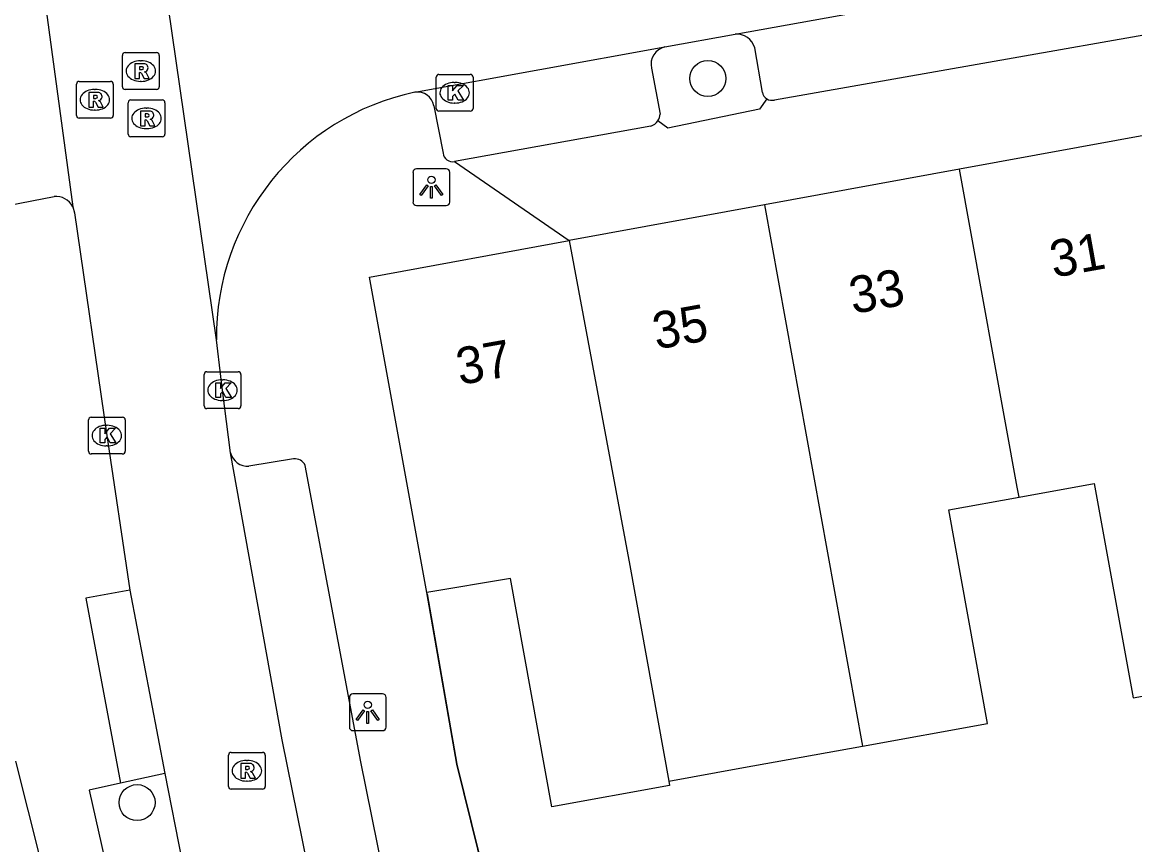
# Model space of a CAD drawing. Extents: x 159718 to 160783, y 383290 to 384030.
# Drawn here: x 160233.32 to 160263.54, y 383643.06 to 383665.41 of the extents above; entities that cross this region are included whole.
import ezdxf

# ---------------------------------------------------------------- set-up
doc = ezdxf.new("R2010")
doc.units = 0
for name, color, linetype in [('IMGEO_Boom', 7, 'Continuous'), ('IMGEO_Kolk', 7, 'Continuous'), ('IMGEO_Lichtpunt', 7, 'Continuous'), ('IMGEO_Muur', 7, 'Continuous'), ('IMGEO_Pand', 7, 'Continuous'), ('IMGEO_Pand_nummerreeks', 7, 'Continuous'), ('IMGEO_Parkeervlak_open', 7, 'Continuous'), ('IMGEO_Rijbaan_lokaal_open', 7, 'Continuous'), ('IMGEO_Rioolput', 7, 'Continuous'), ('IMGEO_Voetpad_open', 7, 'Continuous')]:
    doc.layers.add(name, color=color, linetype=linetype)

msp = doc.modelspace()

# ---------------------------------------------------------------- linework, layer by layer
at = {"layer": 'IMGEO_Boom'}
for centre in [(160251.944, 383663.882), (160236.435, 383644.202)]:
    msp.add_circle(centre, 0.489, dxfattribs=at)
at = {"layer": 'IMGEO_Kolk'}
for p, q in [((160244.563, 383663.069), (160244.563, 383663.921)), ((160244.638, 383663.995), (160245.49, 383663.995)), ((160245.564, 383663.921), (160245.564, 383663.069)), ((160245.051, 383663.775), (160245.076, 383663.775)), ((160245.074, 383663.215), (160245.049, 383663.215)), ((160245.49, 383662.995), (160244.638, 383662.995)), ((160238.257, 383654.986), (160238.257, 383655.838)), ((160238.332, 383655.912), (160239.184, 383655.912)), ((160238.745, 383655.692), (160238.77, 383655.692)), ((160239.258, 383655.838), (160239.258, 383654.986)), ((160238.768, 383655.132), (160238.743, 383655.132)), ((160239.184, 383654.912), (160238.332, 383654.912)), ((160235.114, 383653.751), (160235.114, 383654.603)), ((160235.189, 383654.677), (160236.041, 383654.677)), ((160235.602, 383654.457), (160235.627, 383654.457)), ((160236.115, 383654.603), (160236.115, 383653.751)), ((160235.625, 383653.897), (160235.6, 383653.897)), ((160236.041, 383653.677), (160235.189, 383653.677))]:
    msp.add_line(p, q, dxfattribs=at)
for points in [[(160244.563, 383663.069), (160244.563, 383663.921)], [(160244.638, 383663.995), (160245.49, 383663.995)], [(160245.564, 383663.921), (160245.564, 383663.069)], [(160244.884, 383663.695), (160245.007, 383663.695), (160245.007, 383663.544), (160245.137, 383663.695), (160245.301, 383663.695), (160245.155, 383663.544), (160245.308, 383663.295), (160245.156, 383663.295), (160245.071, 383663.459), (160245.007, 383663.392), (160245.007, 383663.295), (160244.884, 383663.295), (160244.884, 383663.695)], [(160245.49, 383662.995), (160244.638, 383662.995)], [(160238.257, 383654.986), (160238.257, 383655.838)], [(160238.332, 383655.912), (160239.184, 383655.912)], [(160239.258, 383655.838), (160239.258, 383654.986)], [(160238.578, 383655.612), (160238.701, 383655.612), (160238.701, 383655.461), (160238.831, 383655.612), (160238.995, 383655.612), (160238.849, 383655.461), (160239.002, 383655.212), (160238.85, 383655.212), (160238.765, 383655.376), (160238.701, 383655.309), (160238.701, 383655.212), (160238.578, 383655.212), (160238.578, 383655.612)], [(160239.184, 383654.912), (160238.332, 383654.912)], [(160235.114, 383653.751), (160235.114, 383654.603)], [(160235.189, 383654.677), (160236.041, 383654.677)], [(160236.115, 383654.603), (160236.115, 383653.751)], [(160235.435, 383654.377), (160235.558, 383654.377), (160235.558, 383654.226), (160235.688, 383654.377), (160235.852, 383654.377), (160235.706, 383654.226), (160235.859, 383653.977), (160235.707, 383653.977), (160235.622, 383654.141), (160235.558, 383654.074), (160235.558, 383653.977), (160235.435, 383653.977), (160235.435, 383654.377)], [(160236.041, 383653.677), (160235.189, 383653.677)]]:
    msp.add_lwpolyline(points, dxfattribs=at)
for centre, start, end in [((160244.64, 383663.919), 91.552, 178.448), ((160244.64, 383663.919), 91.552, 178.448), ((160245.488, 383663.919), 1.552, 88.448), ((160245.488, 383663.919), 1.552, 88.448), ((160244.64, 383663.071), 181.552, 268.448), ((160244.64, 383663.071), 181.552, 268.448), ((160245.488, 383663.071), 271.552, 358.448), ((160245.488, 383663.071), 271.552, 358.448), ((160238.334, 383655.836), 91.552, 178.448), ((160238.334, 383655.836), 91.552, 178.448), ((160239.182, 383655.836), 1.552, 88.448), ((160239.182, 383655.836), 1.552, 88.448), ((160238.334, 383654.988), 181.552, 268.448), ((160238.334, 383654.988), 181.552, 268.448), ((160239.182, 383654.988), 271.552, 358.448), ((160239.182, 383654.988), 271.552, 358.448), ((160235.191, 383654.601), 91.552, 178.448), ((160235.191, 383654.601), 91.552, 178.448), ((160236.039, 383654.601), 1.552, 88.448), ((160236.039, 383654.601), 1.552, 88.448), ((160235.191, 383653.753), 181.552, 268.448), ((160235.191, 383653.753), 181.552, 268.448), ((160236.039, 383653.753), 271.552, 358.448), ((160236.039, 383653.753), 271.552, 358.448)]:
    msp.add_arc(centre, 0.0765, start, end, dxfattribs=at)
for centre, major_axis, ratio, start_param, end_param in [((160245.05, 383663.495), (-0.387, 0.002), 0.722429, 4.712389, 7.853982), ((160245.075, 383663.495), (-0.39, 0.002), 0.717154, 1.570796, 4.712389), ((160238.744, 383655.412), (-0.387, 0.002), 0.722429, 4.712389, 7.853982), ((160238.769, 383655.412), (-0.39, 0.002), 0.717154, 1.570796, 4.712389), ((160235.601, 383654.177), (-0.387, 0.002), 0.722429, 4.712389, 7.853982), ((160235.626, 383654.177), (-0.39, 0.002), 0.717154, 1.570796, 4.712389)]:
    msp.add_ellipse(centre, major_axis=major_axis, ratio=ratio, start_param=start_param, end_param=end_param, dxfattribs=at)
at = {"layer": 'IMGEO_Lichtpunt'}
for p, q in [((160244.835, 383661.427), (160244.027, 383661.427)), ((160244.835, 383661.427), (160244.027, 383661.427)), ((160243.933, 383661.332), (160243.933, 383660.525)), ((160243.933, 383661.332), (160243.933, 383660.525)), ((160244.929, 383660.525), (160244.929, 383661.332)), ((160244.929, 383660.525), (160244.929, 383661.332)), ((160244.027, 383660.431), (160244.835, 383660.431)), ((160244.027, 383660.431), (160244.835, 383660.431)), ((160242.204, 383647.06), (160242.204, 383646.253)), ((160242.204, 383647.06), (160242.204, 383646.253)), ((160243.106, 383647.155), (160242.298, 383647.155)), ((160243.106, 383647.155), (160242.298, 383647.155)), ((160243.2, 383646.253), (160243.2, 383647.06)), ((160243.2, 383646.253), (160243.2, 383647.06)), ((160242.298, 383646.159), (160243.106, 383646.159)), ((160242.298, 383646.159), (160243.106, 383646.159))]:
    msp.add_line(p, q, dxfattribs=at)
for points in [[(160244.307, 383660.996), (160244.346, 383660.968), (160244.158, 383660.706), (160244.12, 383660.733), (160244.307, 383660.996)], [(160244.409, 383660.948), (160244.456, 383660.948), (160244.456, 383660.626), (160244.409, 383660.626), (160244.409, 383660.948)], [(160244.519, 383660.968), (160244.557, 383660.995), (160244.744, 383660.733), (160244.705, 383660.705), (160244.519, 383660.968)], [(160242.578, 383646.724), (160242.617, 383646.696), (160242.429, 383646.434), (160242.391, 383646.461), (160242.578, 383646.724)], [(160242.68, 383646.676), (160242.727, 383646.676), (160242.727, 383646.354), (160242.68, 383646.354), (160242.68, 383646.676)], [(160242.79, 383646.696), (160242.828, 383646.723), (160243.015, 383646.461), (160242.976, 383646.433), (160242.79, 383646.696)]]:
    msp.add_lwpolyline(points, dxfattribs=at)
for centre in [(160244.432, 383661.13), (160242.703, 383646.858)]:
    msp.add_circle(centre, 0.0994, dxfattribs=at)
for centre, start, end in [((160244.027, 383661.332), 90, 180), ((160244.027, 383661.332), 90, 180), ((160244.835, 383661.332), 0, 90), ((160244.835, 383661.332), 0, 90), ((160244.027, 383660.525), 180, 270), ((160244.027, 383660.525), 180, 270), ((160244.835, 383660.525), 270, 0), ((160244.835, 383660.525), 270, 360), ((160242.298, 383647.06), 90, 180), ((160242.298, 383647.06), 90, 180), ((160243.106, 383647.06), 0, 90), ((160243.106, 383647.06), 0, 90), ((160242.298, 383646.253), 180, 270), ((160242.298, 383646.253), 180, 270), ((160243.106, 383646.253), 270, 0), ((160243.106, 383646.253), 270, 360)]:
    msp.add_arc(centre, 0.0946, start, end, dxfattribs=at)
at = {"layer": 'IMGEO_Muur'}
msp.add_lwpolyline([(160244.315, 383649.879), (160245.119, 383645.245), (160247.129, 383637.151)], dxfattribs=at)
at = {"layer": 'IMGEO_Pand'}
for points in [[(160264.089, 383662.39), (160258.785, 383661.419)], [(160258.785, 383661.419), (160253.482, 383660.448)], [(160260.398, 383652.502), (160260.348, 383652.778), (160258.785, 383661.419)], [(160253.482, 383660.448), (160248.177, 383659.477)], [(160253.482, 383660.448), (160256.142, 383645.739)], [(160244.312, 383649.913), (160242.751, 383658.483), (160248.177, 383659.477)], [(160248.177, 383659.477), (160249.82, 383650.648), (160250.88, 383644.787)], [(160260.398, 383652.502), (160262.443, 383652.872), (160263.497, 383647.05), (160266.757, 383647.64)], [(160256.142, 383645.739), (160259.537, 383646.353), (160258.487, 383652.156), (160260.398, 383652.502)], [(160250.88, 383644.787), (160250.901, 383644.67), (160247.702, 383644.09), (160246.579, 383650.289), (160244.312, 383649.913)], [(160250.88, 383644.787), (160252.816, 383645.137), (160256.142, 383645.739)]]:
    msp.add_lwpolyline(points, dxfattribs=at)
at = {"layer": 'IMGEO_Parkeervlak_open'}
for points in [[(160253.426, 383663.505), (160253.221, 383664.714)], [(160250.409, 383664.16), (160250.647, 383662.914)], [(160244.5, 383663.142), (160244.748, 383661.855)], [(160240.69, 383653.544), (160239.473, 383653.346)], [(160244.249, 383636.832), (160243.736, 383639.271), (160242.519, 383645.31), (160241.004, 383653.362)], [(160247.204, 383636.811), (160245.119, 383645.245), (160244.312, 383649.913)]]:
    msp.add_lwpolyline(points, dxfattribs=at)
for centre, radius, start, end in [((160252.723, 383664.572), 0.517, 15.8985, 94.49), ((160250.897, 383664.259), 0.498, 103.7176, 191.48), ((160244.038, 383663.044), 0.472, 12.0277, 96.4353), ((160253.687, 383663.555), 0.266, 190.8862, 237.401), ((160250.293, 383662.927), 0.355, 326.4031, 357.8578), ((160245.012, 383661.886), 0.265, 186.7069, 280.4993), ((160239.435, 383653.813), 0.469, 193.1083, 274.6857), ((160240.726, 383653.245), 0.301, 22.8706, 96.9347)]:
    msp.add_arc(centre, radius, start, end, dxfattribs=at)
at = {"layer": 'IMGEO_Rijbaan_lokaal_open'}
for points in [[(160238.593, 383656.778), (160236.512, 383671.205), (160236.456, 383671.85)], [(160252.683, 383665.088), (160265.758, 383667.44)], [(160233.748, 383667.351), (160234.686, 383660.399)], [(160250.779, 383664.743), (160252.683, 383665.088)], [(160243.985, 383663.513), (160250.779, 383664.743)], [(160232.968, 383660.44), (160234.18, 383660.672)], [(160234.686, 383660.399), (160234.735, 383660.228), (160235.615, 383654.177), (160236.237, 383649.976)], [(160238.978, 383653.707), (160238.758, 383655.412), (160238.712, 383655.779), (160238.593, 383656.778)], [(160242.451, 383635.672), (160240.374, 383645.912), (160238.978, 383653.707)], [(160236.237, 383649.976), (160235.045, 383649.758), (160235.982, 383644.734)], [(160236.237, 383649.976), (160237.194, 383644.989)], [(160237.374, 383628.936), (160236.476, 383632.08), (160233.141, 383645.332)], [(160237.194, 383644.989), (160237.651, 383642.638)], [(160235.982, 383644.734), (160235.133, 383644.543), (160235.82, 383641.481)]]:
    msp.add_lwpolyline(points, dxfattribs=at)
for centre, radius, start, end in [((160245.412, 383656.844), 6.82, 102.0822, 180.5567), ((160234.241, 383660.179), 0.497, 26.2735, 97.0305)]:
    msp.add_arc(centre, radius, start, end, dxfattribs=at)
at = {"layer": 'IMGEO_Rioolput'}
for p, q in [((160236.037, 383663.659), (160236.037, 383664.511)), ((160236.112, 383664.585), (160236.964, 383664.585)), ((160237.038, 383664.511), (160237.038, 383663.659)), ((160236.525, 383664.365), (160236.55, 383664.365)), ((160234.863, 383663.804), (160235.715, 383663.804)), ((160236.548, 383663.805), (160236.523, 383663.805)), ((160234.788, 383662.878), (160234.788, 383663.73)), ((160235.276, 383663.584), (160235.301, 383663.584)), ((160235.789, 383663.73), (160235.789, 383662.878)), ((160236.964, 383663.585), (160236.112, 383663.585)), ((160236.192, 383662.373), (160236.192, 383663.225)), ((160236.267, 383663.299), (160237.119, 383663.299)), ((160237.193, 383663.225), (160237.193, 383662.373)), ((160235.299, 383663.024), (160235.274, 383663.024)), ((160236.68, 383663.079), (160236.705, 383663.079)), ((160235.715, 383662.804), (160234.863, 383662.804)), ((160237.119, 383662.299), (160236.267, 383662.299)), ((160236.703, 383662.519), (160236.678, 383662.519)), ((160238.919, 383644.641), (160238.919, 383645.493)), ((160238.994, 383645.567), (160239.846, 383645.567)), ((160239.92, 383645.493), (160239.92, 383644.641)), ((160239.407, 383645.347), (160239.432, 383645.347)), ((160239.43, 383644.787), (160239.405, 383644.787)), ((160239.846, 383644.567), (160238.994, 383644.567))]:
    msp.add_line(p, q, dxfattribs=at)
for points in [[(160236.037, 383663.659), (160236.037, 383664.511)], [(160236.112, 383664.585), (160236.964, 383664.585)], [(160237.038, 383664.511), (160237.038, 383663.659)], [(160236.626, 383664.283), (160236.374, 383664.285), (160236.374, 383663.885)], [(160236.552, 383664.204), (160236.498, 383664.204), (160236.498, 383664.123)], [(160236.498, 383664.123), (160236.55, 383664.123)], [(160234.863, 383663.804), (160235.715, 383663.804)], [(160236.374, 383663.885), (160236.498, 383663.885), (160236.498, 383664.047), (160236.509, 383664.047)], [(160236.556, 383664.018), (160236.627, 383663.885), (160236.767, 383663.885), (160236.702, 383664.011)], [(160234.788, 383662.878), (160234.788, 383663.73)], [(160235.377, 383663.502), (160235.125, 383663.504), (160235.125, 383663.104)], [(160235.789, 383663.73), (160235.789, 383662.878)], [(160236.964, 383663.585), (160236.112, 383663.585)], [(160235.125, 383663.104), (160235.249, 383663.104), (160235.249, 383663.266), (160235.26, 383663.266)], [(160235.303, 383663.423), (160235.249, 383663.423), (160235.249, 383663.342)], [(160235.249, 383663.342), (160235.301, 383663.342)], [(160235.307, 383663.237), (160235.378, 383663.104), (160235.518, 383663.104), (160235.453, 383663.23)], [(160236.192, 383662.373), (160236.192, 383663.225)], [(160236.267, 383663.299), (160237.119, 383663.299)], [(160237.193, 383663.225), (160237.193, 383662.373)], [(160236.781, 383662.997), (160236.529, 383662.999), (160236.529, 383662.599)], [(160236.707, 383662.918), (160236.653, 383662.918), (160236.653, 383662.837)], [(160235.715, 383662.804), (160234.863, 383662.804)], [(160236.529, 383662.599), (160236.653, 383662.599), (160236.653, 383662.761), (160236.664, 383662.761)], [(160236.653, 383662.837), (160236.705, 383662.837)], [(160236.711, 383662.732), (160236.782, 383662.599), (160236.922, 383662.599), (160236.857, 383662.725)], [(160237.119, 383662.299), (160236.267, 383662.299)], [(160238.919, 383644.641), (160238.919, 383645.493)], [(160238.994, 383645.567), (160239.846, 383645.567)], [(160239.92, 383645.493), (160239.92, 383644.641)], [(160239.508, 383645.265), (160239.256, 383645.267), (160239.256, 383644.867)], [(160239.434, 383645.186), (160239.38, 383645.186), (160239.38, 383645.105)], [(160239.38, 383645.105), (160239.432, 383645.105)], [(160239.256, 383644.867), (160239.38, 383644.867), (160239.38, 383645.029), (160239.391, 383645.029)], [(160239.438, 383645), (160239.509, 383644.867), (160239.649, 383644.867), (160239.584, 383644.993)], [(160239.846, 383644.567), (160238.994, 383644.567)]]:
    msp.add_lwpolyline(points, dxfattribs=at)
for centre, radius, start, end in [((160236.114, 383664.509), 0.0765, 91.552, 178.448), ((160236.114, 383664.509), 0.0765, 91.552, 178.448), ((160236.962, 383664.509), 0.0765, 1.552, 88.448), ((160236.962, 383664.509), 0.0765, 1.552, 88.448), ((160236.534, 383664.312), 0.19, 274.7715, 282.9687), ((160236.558, 383664.108), 0.0964, 77.0061, 93.1865), ((160236.572, 383664.165), 0.0378, 276.6634, 79.6772), ((160236.625, 383664.173), 0.109, 350.3612, 89.416), ((160236.623, 383664.173), 0.112, 277.5842, 350.9817), ((160234.865, 383663.728), 0.0765, 91.552, 178.448), ((160234.865, 383663.728), 0.0765, 91.552, 178.448), ((160235.713, 383663.728), 0.0765, 1.552, 88.448), ((160235.713, 383663.728), 0.0765, 1.552, 88.448), ((160236.508, 383663.994), 0.0533, 26.0293, 88.6989), ((160236.607, 383663.958), 0.108, 29.5134, 73.7905), ((160235.376, 383663.392), 0.109, 350.3612, 89.416), ((160236.114, 383663.661), 0.0765, 181.552, 268.448), ((160236.114, 383663.661), 0.0765, 181.552, 268.448), ((160236.962, 383663.661), 0.0765, 271.552, 358.448), ((160236.962, 383663.661), 0.0765, 271.552, 358.448), ((160235.259, 383663.213), 0.0533, 26.0293, 88.6989), ((160235.285, 383663.531), 0.19, 274.7715, 282.9687), ((160235.309, 383663.327), 0.0964, 77.0061, 93.1865), ((160235.323, 383663.384), 0.0378, 276.6634, 79.6772), ((160235.374, 383663.392), 0.112, 277.5842, 350.9817), ((160235.358, 383663.177), 0.108, 29.5134, 73.7905), ((160236.269, 383663.223), 0.0765, 91.552, 178.448), ((160236.269, 383663.223), 0.0765, 91.552, 178.448), ((160237.117, 383663.223), 0.0765, 1.552, 88.448), ((160237.117, 383663.223), 0.0765, 1.552, 88.448), ((160236.713, 383662.822), 0.0964, 77.0061, 93.1865), ((160236.727, 383662.879), 0.0378, 276.6634, 79.6772), ((160236.78, 383662.887), 0.109, 350.3612, 89.416), ((160234.865, 383662.88), 0.0765, 181.552, 268.448), ((160234.865, 383662.88), 0.0765, 181.552, 268.448), ((160235.713, 383662.88), 0.0765, 271.552, 358.448), ((160235.713, 383662.88), 0.0765, 271.552, 358.448), ((160236.663, 383662.708), 0.0533, 26.0293, 88.6989), ((160236.689, 383663.026), 0.19, 274.7715, 282.9687), ((160236.778, 383662.887), 0.112, 277.5842, 350.9817), ((160236.762, 383662.672), 0.108, 29.5134, 73.7905), ((160236.269, 383662.375), 0.0765, 181.552, 268.448), ((160236.269, 383662.375), 0.0765, 181.552, 268.448), ((160237.117, 383662.375), 0.0765, 271.552, 358.448), ((160237.117, 383662.375), 0.0765, 271.552, 358.448), ((160238.996, 383645.491), 0.0765, 91.552, 178.448), ((160238.996, 383645.491), 0.0765, 91.552, 178.448), ((160239.844, 383645.491), 0.0765, 1.552, 88.448), ((160239.844, 383645.491), 0.0765, 1.552, 88.448), ((160239.416, 383645.294), 0.19, 274.7715, 282.9687), ((160239.44, 383645.09), 0.0964, 77.0061, 93.1865), ((160239.454, 383645.147), 0.0378, 276.6634, 79.6772), ((160239.507, 383645.155), 0.109, 350.3612, 89.416), ((160239.505, 383645.155), 0.112, 277.5842, 350.9817), ((160239.39, 383644.976), 0.0533, 26.0293, 88.6989), ((160239.489, 383644.94), 0.108, 29.5134, 73.7905), ((160238.996, 383644.643), 0.0765, 181.552, 268.448), ((160238.996, 383644.643), 0.0765, 181.552, 268.448), ((160239.844, 383644.643), 0.0765, 271.552, 358.448), ((160239.844, 383644.643), 0.0765, 271.552, 358.448)]:
    msp.add_arc(centre, radius, start, end, dxfattribs=at)
for centre, major_axis, ratio, start_param, end_param in [((160236.524, 383664.085), (-0.387, 0.002), 0.722429, 4.712389, 7.853982), ((160236.549, 383664.085), (-0.39, 0.002), 0.717154, 1.570796, 4.712389), ((160235.275, 383663.304), (-0.387, 0.002), 0.722429, 4.712389, 7.853982), ((160235.3, 383663.304), (-0.39, 0.002), 0.717154, 1.570796, 4.712389), ((160236.679, 383662.799), (-0.387, 0.002), 0.722429, 4.712389, 7.853982), ((160236.704, 383662.799), (-0.39, 0.002), 0.717154, 1.570796, 4.712389), ((160239.406, 383645.067), (-0.387, 0.002), 0.722429, 4.712389, 7.853982), ((160239.431, 383645.067), (-0.39, 0.002), 0.717154, 1.570796, 4.712389)]:
    msp.add_ellipse(centre, major_axis=major_axis, ratio=ratio, start_param=start_param, end_param=end_param, dxfattribs=at)
at = {"layer": 'IMGEO_Voetpad_open'}
for points in [[(160270.429, 383666.237), (160253.75, 383663.297)], [(160253.544, 383663.331), (160253.351, 383663.045), (160250.859, 383662.535), (160250.588, 383662.731)], [(160250.392, 383662.59), (160245.06, 383661.625)], [(160245.06, 383661.625), (160248.177, 383659.477)], [(160237.194, 383644.989), (160235.982, 383644.734)]]:
    msp.add_lwpolyline(points, dxfattribs=at)
for centre, radius, start, end in [((160253.687, 383663.557), 0.268, 237.66, 283.5958), ((160250.301, 383662.923), 0.345, 285.2607, 326.2008)]:
    msp.add_arc(centre, radius, start, end, dxfattribs=at)

# ---------------------------------------------------------------- texts
at = {"layer": 'IMGEO_Pand_nummerreeks'}
for s, p in [('31', (160261.334, 383658.465)), ('33', (160255.883, 383657.479)), ('35', (160250.544, 383656.513)), ('37', (160245.205, 383655.547))]:
    msp.add_text(s, height=1, rotation=10.2559, dxfattribs=at).set_placement(p)

doc.saveas('drawing.dxf')
